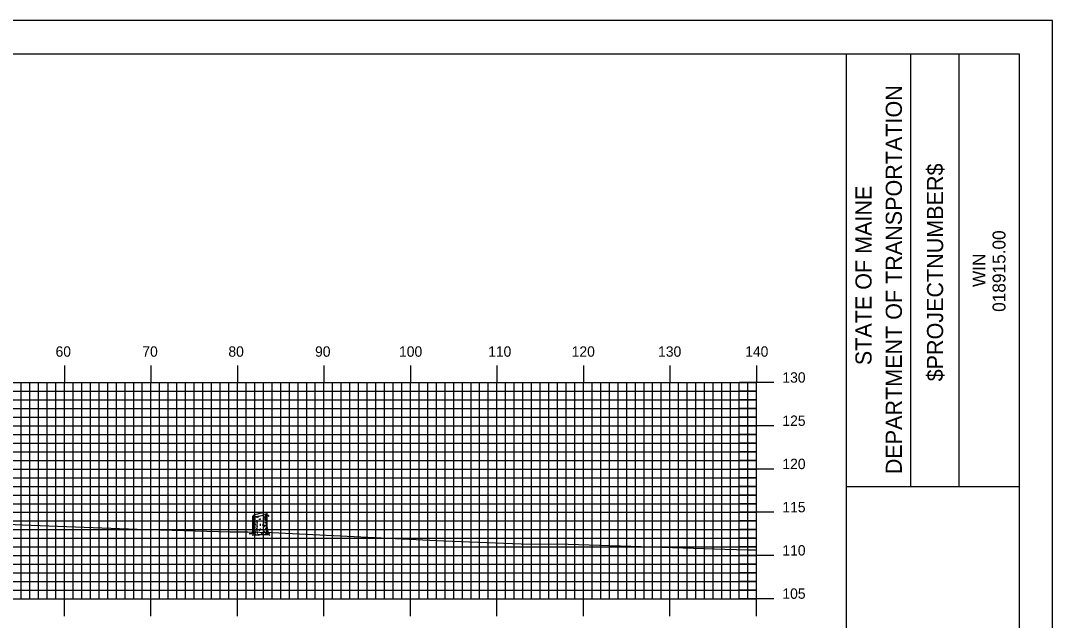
# Model space of a CAD drawing. Extents: x 1771235 to 1771579, y 442591 to 442811.
# Drawn here: x 1771456 to 1771575.3, y 442741.2 to 442810.5 of the extents above; entities that cross this region are included whole.
import ezdxf

# ---------------------------------------------------------------- set-up
doc = ezdxf.new("R2010")
doc.units = 0
for name, color, linetype in [('BORDER', 7, 'Continuous'), ('H_V ANNOTATION', 7, 'Continuous'), ('M_Trees_Conifer_Pay', 7, 'Continuous'), ('MAJOR', 7, 'Continuous'), ('MINOR', 7, 'Continuous'), ('PLOT BOUNDARY', 7, 'Continuous'), ('S_Roadway_Centerline', 7, 'Continuous')]:
    doc.layers.add(name, color=color, linetype=linetype)

msp = doc.modelspace()

# ---------------------------------------------------------------- linework, layer by layer
at = {"layer": 'BORDER'}
for p, q in [((1771551.47, 442596.67), (1771551.47, 442806.67)), ((1771558.92, 442756.66), (1771558.92, 442806.66)), ((1771564.51, 442756.66), (1771564.51, 442806.66)), ((1771551.47, 442756.65), (1771571.47, 442756.65))]:
    msp.add_line(p, q, dxfattribs=at)
msp.add_lwpolyline([(1771251.47, 442596.67), (1771571.47, 442596.67), (1771571.47, 442806.67), (1771251.47, 442806.67)], close=True, dxfattribs=at)
at = {"layer": 'M_Trees_Conifer_Pay'}
for p, q in [((1771482.85, 442751.5), (1771482.85, 442753.22)), ((1771482.89, 442753.19), (1771482.89, 442752.72)), ((1771482.95, 442753.18), (1771482.95, 442753.08)), ((1771482.95, 442753), (1771482.95, 442752.8)), ((1771483.08, 442753.17), (1771483.08, 442752.94)), ((1771483.08, 442752.9), (1771483.08, 442752.82)), ((1771483.3, 442753.19), (1771483.3, 442753.02)), ((1771483.3, 442752.78), (1771483.3, 442752.55)), ((1771483.7, 442752.96), (1771483.7, 442752.86)), ((1771484.09, 442753.23), (1771484.09, 442753.03)), ((1771484.09, 442752.97), (1771484.09, 442752.89)), ((1771484.32, 442753.43), (1771484.32, 442753.2)), ((1771484.32, 442753.12), (1771484.32, 442753.07)), ((1771484.38, 442752.93), (1771484.33, 442752.87)), ((1771484.44, 442753.49), (1771484.44, 442753.33)), ((1771484.44, 442753.26), (1771484.44, 442753.13)), ((1771484.44, 442752.94), (1771484.44, 442752.61)), ((1771484.51, 442751.91), (1771484.51, 442753.56)), ((1771482.89, 442752.65), (1771482.89, 442752.34)), ((1771482.89, 442752.3), (1771482.89, 442751.8)), ((1771482.89, 442751.75), (1771482.89, 442751.5)), ((1771482.95, 442752.74), (1771482.95, 442752.54)), ((1771482.95, 442752.5), (1771482.95, 442752.16)), ((1771482.95, 442752.11), (1771482.95, 442751.97)), ((1771482.95, 442751.87), (1771482.95, 442751.49)), ((1771483.08, 442752.42), (1771483.08, 442752.28)), ((1771483.08, 442752.01), (1771483.08, 442751.87)), ((1771483.08, 442751.6), (1771483.08, 442751.51)), ((1771483.3, 442752.3), (1771483.3, 442752.15)), ((1771483.3, 442752.11), (1771483.3, 442751.93)), ((1771483.3, 442751.66), (1771483.3, 442751.5)), ((1771483.7, 442752.34), (1771483.7, 442752.27)), ((1771483.7, 442752.24), (1771483.7, 442752.1)), ((1771483.7, 442751.8), (1771483.7, 442751.65)), ((1771484.09, 442752.54), (1771484.09, 442752.43)), ((1771484.09, 442752.07), (1771484.09, 442751.92)), ((1771484.09, 442751.69), (1771484.09, 442751.6)), ((1771484.32, 442752.73), (1771484.32, 442752.6)), ((1771484.32, 442752.49), (1771484.32, 442752.38)), ((1771484.32, 442752.24), (1771484.32, 442752.1)), ((1771484.32, 442751.88), (1771484.32, 442751.7)), ((1771484.44, 442752.57), (1771484.44, 442752.41)), ((1771484.44, 442752.36), (1771484.44, 442752.14)), ((1771484.44, 442752.11), (1771484.44, 442752.04)), ((1771484.44, 442752), (1771484.44, 442751.82)), ((1771483.08, 442751.11), (1771483.24, 442751.17)), ((1771483.52, 442751.05), (1771483.39, 442751.11))]:
    msp.add_line(p, q, dxfattribs=at)
for points in [[(1771484.29, 442753.02), (1771484.26, 442752.94), (1771484.26, 442752.87), (1771484.29, 442752.8)], [(1771484.33, 442753.06), (1771484.36, 442752.98), (1771484.41, 442753.04), (1771484.47, 442753.11), (1771484.56, 442753.3), (1771484.63, 442753.35), (1771484.66, 442753.36)], [(1771484.34, 442752.8), (1771484.38, 442752.93), (1771484.44, 442753.05), (1771484.47, 442753.12), (1771484.54, 442753.26)], [(1771484.56, 442753.29), (1771484.63, 442753.3), (1771484.7, 442753.2)], [(1771484.51, 442751.91), (1771484.56, 442751.65), (1771484.58, 442751.38), (1771484.64, 442751.25), (1771484.77, 442751.22), (1771484.54, 442751.18), (1771484.54, 442751.18), (1771484.55, 442751.14), (1771484.8, 442751.04), (1771484.52, 442751.06), (1771484.17, 442751.08), (1771483.84, 442751.07), (1771483.85, 442751.15), (1771483.7, 442751.07), (1771483.52, 442751.05), (1771483.54, 442750.98), (1771483.27, 442751.02), (1771483.05, 442750.99), (1771482.76, 442751.01), (1771483.05, 442751.07), (1771483.08, 442751.11), (1771482.92, 442751.17), (1771482.68, 442751.18), (1771482.44, 442751.18), (1771482.78, 442751.24), (1771482.82, 442751.32), (1771482.85, 442751.5)], [(1771483.03, 442752.53), (1771483.02, 442752.63), (1771483.06, 442752.6), (1771483.06, 442752.51)], [(1771484.17, 442752.13), (1771484.18, 442752.05), (1771484.23, 442752.07), (1771484.21, 442752.23)], [(1771484.34, 442751.63), (1771484.41, 442751.52), (1771484.42, 442751.35), (1771484.54, 442751.18)], [(1771484.44, 442751.77), (1771484.44, 442751.63), (1771484.49, 442751.56), (1771484.5, 442751.36)], [(1771482.9, 442751.46), (1771482.87, 442751.38), (1771482.85, 442751.28)], [(1771482.97, 442751.44), (1771482.98, 442751.32), (1771482.93, 442751.23), (1771482.92, 442751.17)], [(1771483.14, 442751.46), (1771483.14, 442751.33), (1771483.05, 442751.23)], [(1771483.36, 442751.22), (1771483.43, 442751.32), (1771483.46, 442751.46)], [(1771483.85, 442751.15), (1771483.92, 442751.29), (1771483.93, 442751.39)], [(1771484.1, 442751.52), (1771484.11, 442751.39), (1771484.19, 442751.35)], [(1771484.38, 442751.13), (1771484.36, 442751.27), (1771484.29, 442751.4)]]:
    msp.add_lwpolyline(points, dxfattribs=at)
for centre, radius, start, end in [((1771482.92, 442753.2), 0.0817, 132.3887, 146.7194), ((1771482.9, 442753.22), 0.0527, 146.7194, 156.5158), ((1771482.88, 442753.22), 0.0314, 156.5158, 169.2194), ((1771482.87, 442753.22), 0.0264, 169.2194, 180.0315), ((1771482.87, 442753.22), 0.0226, 180.0315, 191.7194), ((1771482.87, 442753.22), 0.0226, 191.7194, 203.4074), ((1771482.87, 442753.23), 0.0264, 203.4074, 214.2194), ((1771482.88, 442753.23), 0.0314, 214.2194, 226.923), ((1771482.88, 442753.05), 0.0334, 163.9485, 180), ((1771482.88, 442753.05), 0.0334, 180, 196.0515), ((1771482.89, 442753.05), 0.0441, 196.0515, 210), ((1771482.91, 442753.06), 0.0624, 210, 228.7494), ((1771482.89, 442753.24), 0.0527, 226.923, 236.7194), ((1771482.91, 442753.27), 0.0817, 236.7194, 251.0501), ((1771482.98, 442753.14), 0.172, 228.7494, 240), ((1771483.04, 442753.07), 0.251, 124.2194, 132.3887), ((1771482.96, 442753.43), 0.251, 251.0501, 259.2194), ((1771483.18, 442753.49), 0.571, 240, 240.3367), ((1771483.35, 442752.62), 0.802, 108.0594, 124.2194), ((1771483.07, 442753.97), 0.802, 259.2194, 275.3794), ((1771483.18, 442753.49), 0.571, 246.8597, 257.9846), ((1771484.7, 442748.46), 5.18, 101.7194, 108.0594), ((1771482.66, 442758.33), 5.18, 275.3794, 281.7194), ((1771483.68, 442757.24), 4.12, 264.6955, 266.7331), ((1771483.68, 442757), 4.12, 268.0751, 270), ((1771484.7, 442748.46), 5.18, 95.3794, 101.7194), ((1771483.68, 442757), 4.12, 270, 270.3581), ((1771482.66, 442758.33), 5.18, 281.7194, 288.0594), ((1771483.68, 442757), 4.12, 275.7849, 277.0558), ((1771483.68, 442757.24), 4.12, 276.238, 278.1032), ((1771484.29, 442752.82), 0.802, 79.2194, 95.3794), ((1771484.01, 442754.17), 0.802, 288.0594, 304.2194), ((1771484.18, 442753.72), 0.571, 278.1032, 284.3667), ((1771484.18, 442753.87), 0.571, 284.4317, 292.4132), ((1771484.4, 442753.36), 0.251, 71.0501, 79.2194), ((1771484.18, 442753.72), 0.571, 297.0237, 300), ((1771484.32, 442753.71), 0.251, 304.2194, 312.3887), ((1771484.38, 442753.53), 0.172, 300, 311.2506), ((1771484.38, 442753.37), 0.172, 300, 311.2506), ((1771484.45, 442753.52), 0.0817, 56.7194, 71.0501), ((1771484.44, 442753.59), 0.0817, 312.3887, 326.7194), ((1771484.45, 442753.45), 0.0624, 311.2506, 330), ((1771484.45, 442753.29), 0.0624, 311.2506, 330), ((1771484.48, 442753.56), 0.0314, 34.2194, 46.923), ((1771484.47, 442753.54), 0.0527, 46.923, 56.7194), ((1771484.46, 442753.57), 0.0527, 326.7194, 336.5158), ((1771484.49, 442753.56), 0.0226, 11.7194, 23.4074), ((1771484.49, 442753.56), 0.0264, 23.4074, 34.2194), ((1771484.49, 442753.56), 0.0226, 0.0315, 11.7194), ((1771484.48, 442753.56), 0.0314, 336.5158, 349.2194), ((1771484.48, 442753.56), 0.0264, 349.2194, 0.0315), ((1771484.48, 442753.43), 0.0334, 343.9485, 354.2151), ((1771484.47, 442753.44), 0.0441, 330, 343.9485), ((1771484.48, 442753.28), 0.0334, 343.9485, 354.2151), ((1771484.47, 442753.28), 0.0441, 330, 343.9485), ((1771484.48, 442752.84), 0.0334, 343.9485, 354.2151), ((1771482.88, 442752.6), 0.0334, 163.9485, 180), ((1771482.88, 442752.6), 0.0334, 180, 196.0515), ((1771482.89, 442752.6), 0.0441, 196.0515, 210), ((1771482.91, 442752.61), 0.0624, 210, 228.7494), ((1771482.88, 442752.39), 0.0334, 163.9485, 180), ((1771482.88, 442752.39), 0.0334, 180, 196.0515), ((1771482.89, 442752.39), 0.0441, 196.0515, 210), ((1771482.91, 442752.4), 0.0624, 210, 228.7494), ((1771482.88, 442752.15), 0.0334, 163.9485, 180), ((1771482.88, 442752.15), 0.0334, 180, 196.0515), ((1771482.89, 442752.16), 0.0441, 196.0515, 210), ((1771482.91, 442752.17), 0.0624, 210, 228.7494), ((1771482.88, 442751.96), 0.0334, 163.9485, 180), ((1771482.88, 442751.76), 0.0334, 163.9485, 180), ((1771482.88, 442751.76), 0.0334, 180, 196.0515), ((1771482.89, 442751.76), 0.0441, 196.0515, 210), ((1771482.91, 442751.77), 0.0624, 210, 228.7494), ((1771482.98, 442752.69), 0.172, 228.7494, 240), ((1771482.98, 442752.48), 0.172, 228.7494, 240), ((1771482.98, 442752.25), 0.172, 228.7494, 240), ((1771482.98, 442751.85), 0.172, 228.7494, 240), ((1771483.18, 442753.28), 0.571, 240, 247.0587), ((1771483.18, 442753.04), 0.571, 240, 240.3367), ((1771483.18, 442752.83), 0.571, 240, 246.8597), ((1771483.18, 442752.59), 0.571, 240, 246.8597), ((1771483.17, 442752.4), 0.571, 241.2369, 248.0268), ((1771483.18, 442752.2), 0.571, 240, 246.8597), ((1771483.18, 442752.83), 0.571, 259.2707, 261.8968), ((1771483.68, 442756.35), 4.12, 261.8968, 263.1474), ((1771483.68, 442755.91), 4.12, 263.4991, 265.8397), ((1771483.68, 442756.56), 4.12, 264.081, 266.6676), ((1771483.68, 442756.11), 4.12, 264.716, 266.3193), ((1771483.68, 442755.72), 4.12, 267.8117, 270), ((1771483.68, 442756.35), 4.12, 270, 270.3581), ((1771483.68, 442755.72), 4.12, 270, 270.1328), ((1771483.68, 442756.35), 4.12, 273.1493, 275.4569), ((1771483.68, 442756.79), 4.12, 273.7052, 275.9504), ((1771483.68, 442755.72), 4.12, 275.7849, 276.7896), ((1771483.68, 442756.56), 4.12, 277.6125, 278.1032), ((1771484.18, 442753.04), 0.571, 278.1032, 286.9296), ((1771484.18, 442753.28), 0.571, 284.4493, 297.0429), ((1771484.18, 442752.59), 0.571, 285.3983, 297.1896), ((1771484.18, 442752.2), 0.571, 288.5067, 297.2721), ((1771484.18, 442752.4), 0.571, 289.2907, 300), ((1771484.18, 442753.04), 0.571, 297.1896, 300), ((1771484.18, 442752.83), 0.571, 297.1896, 300), ((1771484.38, 442752.69), 0.172, 300, 311.2506), ((1771484.38, 442752.48), 0.172, 300, 311.2506), ((1771484.38, 442752.05), 0.172, 300, 311.2506), ((1771484.45, 442752.61), 0.0624, 311.2506, 330), ((1771484.45, 442752.4), 0.0624, 311.2506, 330), ((1771484.45, 442751.97), 0.0624, 311.2506, 330), ((1771484.47, 442752.6), 0.0441, 330, 343.9485), ((1771484.47, 442752.39), 0.0441, 330, 343.9485), ((1771484.47, 442751.96), 0.0441, 330, 343.9485), ((1771484.48, 442752.6), 0.0334, 343.9485, 354.2151), ((1771484.48, 442752.39), 0.0334, 343.9485, 354.2151), ((1771484.48, 442751.96), 0.0334, 343.9485, 354.2151), ((1771482.88, 442751.54), 0.0334, 163.9485, 180), ((1771482.88, 442751.54), 0.0334, 180, 196.0515), ((1771482.89, 442751.54), 0.0441, 196.0515, 210), ((1771482.91, 442751.55), 0.0624, 210, 228.7494), ((1771482.98, 442751.63), 0.172, 228.7494, 240), ((1771483.18, 442751.98), 0.571, 240, 244.5314), ((1771483.68, 442755.5), 4.12, 262.4438, 263.512), ((1771483.68, 442755.5), 4.12, 277.3684, 278.1032), ((1771484.18, 442751.98), 0.571, 278.1032, 281.637), ((1771484.38, 442751.63), 0.172, 300, 311.2506), ((1771484.45, 442751.55), 0.0624, 311.2506, 330), ((1771484.47, 442751.54), 0.0441, 330, 343.9485), ((1771484.48, 442751.54), 0.0334, 343.9485, 354.2151)]:
    msp.add_arc(centre, radius, start, end, dxfattribs=at)
at = {"layer": 'MAJOR'}
for p, q in [((1771461.07, 442770.67), (1771461.07, 442768.67)), ((1771471.07, 442770.67), (1771471.07, 442768.67)), ((1771481.07, 442770.67), (1771481.07, 442768.67)), ((1771491.07, 442770.67), (1771491.07, 442768.67)), ((1771501.07, 442770.67), (1771501.07, 442768.67)), ((1771511.07, 442770.67), (1771511.07, 442768.67)), ((1771521.07, 442770.67), (1771521.07, 442768.67)), ((1771531.07, 442770.67), (1771531.07, 442768.67)), ((1771541.07, 442770.67), (1771541.07, 442768.67)), ((1771261.07, 442768.67), (1771541.07, 442768.67)), ((1771261.07, 442768.67), (1771541.07, 442768.67)), ((1771461.07, 442743.67), (1771461.07, 442768.67)), ((1771471.07, 442743.67), (1771471.07, 442768.67)), ((1771481.07, 442743.67), (1771481.07, 442768.67)), ((1771491.07, 442743.67), (1771491.07, 442768.67)), ((1771501.07, 442743.67), (1771501.07, 442768.67)), ((1771511.07, 442743.67), (1771511.07, 442768.67)), ((1771521.07, 442743.67), (1771521.07, 442768.67)), ((1771531.07, 442743.67), (1771531.07, 442768.67)), ((1771543.07, 442768.67), (1771539.06, 442768.67)), ((1771541.07, 442743.67), (1771541.07, 442768.67)), ((1771541.07, 442743.67), (1771541.07, 442768.67)), ((1771261.07, 442763.67), (1771541.07, 442763.67)), ((1771543.07, 442763.67), (1771539.06, 442763.67)), ((1771261.07, 442758.67), (1771541.07, 442758.67)), ((1771543.07, 442758.67), (1771539.06, 442758.67)), ((1771261.07, 442753.67), (1771541.07, 442753.67)), ((1771543.07, 442753.67), (1771539.06, 442753.67)), ((1771261.07, 442748.67), (1771541.07, 442748.67)), ((1771543.07, 442748.67), (1771539.06, 442748.67)), ((1771261.07, 442743.67), (1771541.07, 442743.67)), ((1771261.07, 442743.67), (1771541.07, 442743.67)), ((1771461.07, 442741.66), (1771461.07, 442743.67)), ((1771471.07, 442741.66), (1771471.07, 442743.67)), ((1771481.07, 442741.66), (1771481.07, 442743.67)), ((1771491.07, 442741.66), (1771491.07, 442743.67)), ((1771501.07, 442741.66), (1771501.07, 442743.67)), ((1771511.07, 442741.66), (1771511.07, 442743.67)), ((1771521.07, 442741.66), (1771521.07, 442743.67)), ((1771531.07, 442741.66), (1771531.07, 442743.67)), ((1771543.07, 442743.67), (1771539.06, 442743.67)), ((1771541.07, 442741.66), (1771541.07, 442743.67))]:
    msp.add_line(p, q, dxfattribs=at)
at = {"layer": 'MINOR'}
for p, q in [((1771456.07, 442743.67), (1771456.07, 442768.67)), ((1771457.07, 442743.67), (1771457.07, 442768.67)), ((1771458.07, 442743.67), (1771458.07, 442768.67)), ((1771459.07, 442743.67), (1771459.07, 442768.67)), ((1771460.07, 442743.67), (1771460.07, 442768.67)), ((1771462.07, 442743.67), (1771462.07, 442768.67)), ((1771463.07, 442743.67), (1771463.07, 442768.67)), ((1771464.07, 442743.67), (1771464.07, 442768.67)), ((1771465.07, 442743.67), (1771465.07, 442768.67)), ((1771466.07, 442743.67), (1771466.07, 442768.67)), ((1771467.07, 442743.67), (1771467.07, 442768.67)), ((1771468.07, 442743.67), (1771468.07, 442768.67)), ((1771469.07, 442743.67), (1771469.07, 442768.67)), ((1771470.07, 442743.67), (1771470.07, 442768.67)), ((1771472.07, 442743.67), (1771472.07, 442768.67)), ((1771473.07, 442743.67), (1771473.07, 442768.67)), ((1771474.07, 442743.67), (1771474.07, 442768.67)), ((1771475.07, 442743.67), (1771475.07, 442768.67)), ((1771476.07, 442743.67), (1771476.07, 442768.67)), ((1771477.07, 442743.67), (1771477.07, 442768.67)), ((1771478.07, 442743.67), (1771478.07, 442768.67)), ((1771479.07, 442743.67), (1771479.07, 442768.67)), ((1771480.07, 442743.67), (1771480.07, 442768.67)), ((1771482.07, 442743.67), (1771482.07, 442768.67)), ((1771483.07, 442743.67), (1771483.07, 442768.67)), ((1771484.07, 442743.67), (1771484.07, 442768.67)), ((1771485.07, 442743.67), (1771485.07, 442768.67)), ((1771486.07, 442743.67), (1771486.07, 442768.67)), ((1771487.07, 442743.67), (1771487.07, 442768.67)), ((1771488.07, 442743.67), (1771488.07, 442768.67)), ((1771489.07, 442743.67), (1771489.07, 442768.67)), ((1771490.07, 442743.67), (1771490.07, 442768.67)), ((1771492.07, 442743.67), (1771492.07, 442768.67)), ((1771493.07, 442743.67), (1771493.07, 442768.67)), ((1771494.07, 442743.67), (1771494.07, 442768.67)), ((1771495.07, 442743.67), (1771495.07, 442768.67)), ((1771496.07, 442743.67), (1771496.07, 442768.67)), ((1771497.07, 442743.67), (1771497.07, 442768.67)), ((1771498.07, 442743.67), (1771498.07, 442768.67)), ((1771499.07, 442743.67), (1771499.07, 442768.67)), ((1771500.07, 442743.67), (1771500.07, 442768.67)), ((1771502.07, 442743.67), (1771502.07, 442768.67)), ((1771503.07, 442743.67), (1771503.07, 442768.67)), ((1771504.07, 442743.67), (1771504.07, 442768.67)), ((1771505.07, 442743.67), (1771505.07, 442768.67)), ((1771506.07, 442743.67), (1771506.07, 442768.67)), ((1771507.07, 442743.67), (1771507.07, 442768.67)), ((1771508.07, 442743.67), (1771508.07, 442768.67)), ((1771509.07, 442743.67), (1771509.07, 442768.67)), ((1771510.07, 442743.67), (1771510.07, 442768.67)), ((1771512.07, 442743.67), (1771512.07, 442768.67)), ((1771513.07, 442743.67), (1771513.07, 442768.67)), ((1771514.07, 442743.67), (1771514.07, 442768.67)), ((1771515.07, 442743.67), (1771515.07, 442768.67)), ((1771516.07, 442743.67), (1771516.07, 442768.67)), ((1771517.07, 442743.67), (1771517.07, 442768.67)), ((1771518.07, 442743.67), (1771518.07, 442768.67)), ((1771519.07, 442743.67), (1771519.07, 442768.67)), ((1771520.07, 442743.67), (1771520.07, 442768.67)), ((1771522.07, 442743.67), (1771522.07, 442768.67)), ((1771523.07, 442743.67), (1771523.07, 442768.67)), ((1771524.07, 442743.67), (1771524.07, 442768.67)), ((1771525.07, 442743.67), (1771525.07, 442768.67)), ((1771526.07, 442743.67), (1771526.07, 442768.67)), ((1771527.07, 442743.67), (1771527.07, 442768.67)), ((1771528.07, 442743.67), (1771528.07, 442768.67)), ((1771529.07, 442743.67), (1771529.07, 442768.67)), ((1771530.07, 442743.67), (1771530.07, 442768.67)), ((1771532.07, 442743.67), (1771532.07, 442768.67)), ((1771533.07, 442743.67), (1771533.07, 442768.67)), ((1771534.07, 442743.67), (1771534.07, 442768.67)), ((1771535.07, 442743.67), (1771535.07, 442768.67)), ((1771536.07, 442743.67), (1771536.07, 442768.67)), ((1771537.07, 442743.67), (1771537.07, 442768.67)), ((1771538.07, 442743.67), (1771538.07, 442768.67)), ((1771539.07, 442743.67), (1771539.07, 442768.67)), ((1771540.07, 442743.67), (1771540.07, 442768.67)), ((1771261.07, 442767.67), (1771541.07, 442767.67)), ((1771541.07, 442767.67), (1771539.06, 442767.67)), ((1771261.07, 442766.67), (1771541.07, 442766.67)), ((1771541.07, 442766.67), (1771539.06, 442766.67)), ((1771261.07, 442765.67), (1771541.07, 442765.67)), ((1771541.07, 442765.67), (1771539.06, 442765.67)), ((1771261.07, 442764.67), (1771541.07, 442764.67)), ((1771541.07, 442764.67), (1771539.06, 442764.67)), ((1771261.07, 442762.67), (1771541.07, 442762.67)), ((1771541.07, 442762.67), (1771539.06, 442762.67)), ((1771261.07, 442761.67), (1771541.07, 442761.67)), ((1771541.07, 442761.67), (1771539.06, 442761.67)), ((1771261.07, 442760.67), (1771541.07, 442760.67)), ((1771541.07, 442760.67), (1771539.06, 442760.67)), ((1771261.07, 442759.67), (1771541.07, 442759.67)), ((1771541.07, 442759.67), (1771539.06, 442759.67)), ((1771261.07, 442757.67), (1771541.07, 442757.67)), ((1771541.07, 442757.67), (1771539.06, 442757.67)), ((1771261.07, 442756.67), (1771541.07, 442756.67)), ((1771541.07, 442756.67), (1771539.06, 442756.67)), ((1771261.07, 442755.67), (1771541.07, 442755.67)), ((1771541.07, 442755.67), (1771539.06, 442755.67)), ((1771261.07, 442754.67), (1771541.07, 442754.67)), ((1771541.07, 442754.67), (1771539.06, 442754.67)), ((1771261.07, 442752.67), (1771541.07, 442752.67)), ((1771261.07, 442751.67), (1771541.07, 442751.67)), ((1771541.07, 442752.67), (1771539.06, 442752.67)), ((1771541.07, 442751.67), (1771539.06, 442751.67)), ((1771261.07, 442750.67), (1771541.07, 442750.67)), ((1771541.07, 442750.67), (1771539.06, 442750.67)), ((1771261.07, 442749.67), (1771541.07, 442749.67)), ((1771541.07, 442749.67), (1771539.06, 442749.67)), ((1771261.07, 442747.67), (1771541.07, 442747.67)), ((1771541.07, 442747.67), (1771539.06, 442747.67)), ((1771261.07, 442746.67), (1771541.07, 442746.67)), ((1771261.07, 442745.67), (1771541.07, 442745.67)), ((1771541.07, 442746.67), (1771539.06, 442746.67)), ((1771541.07, 442745.67), (1771539.06, 442745.67)), ((1771261.07, 442744.67), (1771541.07, 442744.67)), ((1771541.07, 442744.67), (1771539.06, 442744.67))]:
    msp.add_line(p, q, dxfattribs=at)
at = {"layer": 'PLOT BOUNDARY'}
msp.add_lwpolyline([(1771235.28, 442590.55), (1771575.28, 442590.55), (1771575.28, 442810.55), (1771235.28, 442810.55)], close=True, dxfattribs=at)
at = {"layer": 'S_Roadway_Centerline'}
msp.add_lwpolyline([(1771438.51, 442753.02), (1771456.22, 442752.22), (1771458.26, 442752.15), (1771469.49, 442751.72), (1771480.23, 442751.42), (1771482.27, 442751.4), (1771485.03, 442751.34), (1771499.29, 442750.64), (1771504.92, 442750.37), (1771513.85, 442750.01), (1771519.32, 442749.97), (1771537.4, 442749.4), (1771540.1, 442749.34), (1771540.48, 442749.32), (1771540.92, 442749.32), (1771541.07, 442749.31)], dxfattribs=at)

# ---------------------------------------------------------------- texts
at = {"layer": 'BORDER'}
for s, height, p in [('DEPARTMENT OF TRANSPORTATION', 1.8635, (1771557.88, 442758.08)), ('$PROJECTNUMBER$', 1.8635, (1771562.65, 442768.82)), ('STATE OF MAINE', 1.8635, (1771554.38, 442770.69)), ('018915.00', 1.491, (1771569.86, 442776.86)), ('WIN', 1.491, (1771567.54, 442779.73))]:
    msp.add_text(s, height=height, rotation=90, dxfattribs=at).set_placement(p)
at = {"layer": 'H_V ANNOTATION'}
for s, p in [('60', (1771460.04, 442771.67)), ('70', (1771470.07, 442771.67)), ('80', (1771480.02, 442771.67)), ('90', (1771490.04, 442771.67)), ('100', (1771499.75, 442771.67)), ('110', (1771510.05, 442771.67)), ('120', (1771519.71, 442771.67)), ('130', (1771529.7, 442771.67)), ('140', (1771539.77, 442771.67)), ('130', (1771544.07, 442768.67)), ('125', (1771544.07, 442763.67)), ('120', (1771544.07, 442758.67)), ('115', (1771544.07, 442753.67)), ('110', (1771544.07, 442748.67)), ('105', (1771544.07, 442743.67))]:
    msp.add_text(s, height=1.2, dxfattribs=at).set_placement(p)

doc.saveas('drawing.dxf')
